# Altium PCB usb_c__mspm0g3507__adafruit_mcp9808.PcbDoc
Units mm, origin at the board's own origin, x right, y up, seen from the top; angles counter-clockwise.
Board outline 92 x 60 mm, 2 copper layers (Top, Bottom), stack 0 mm thick; 37 components, 30 nets, 190 pads, 49 vias.
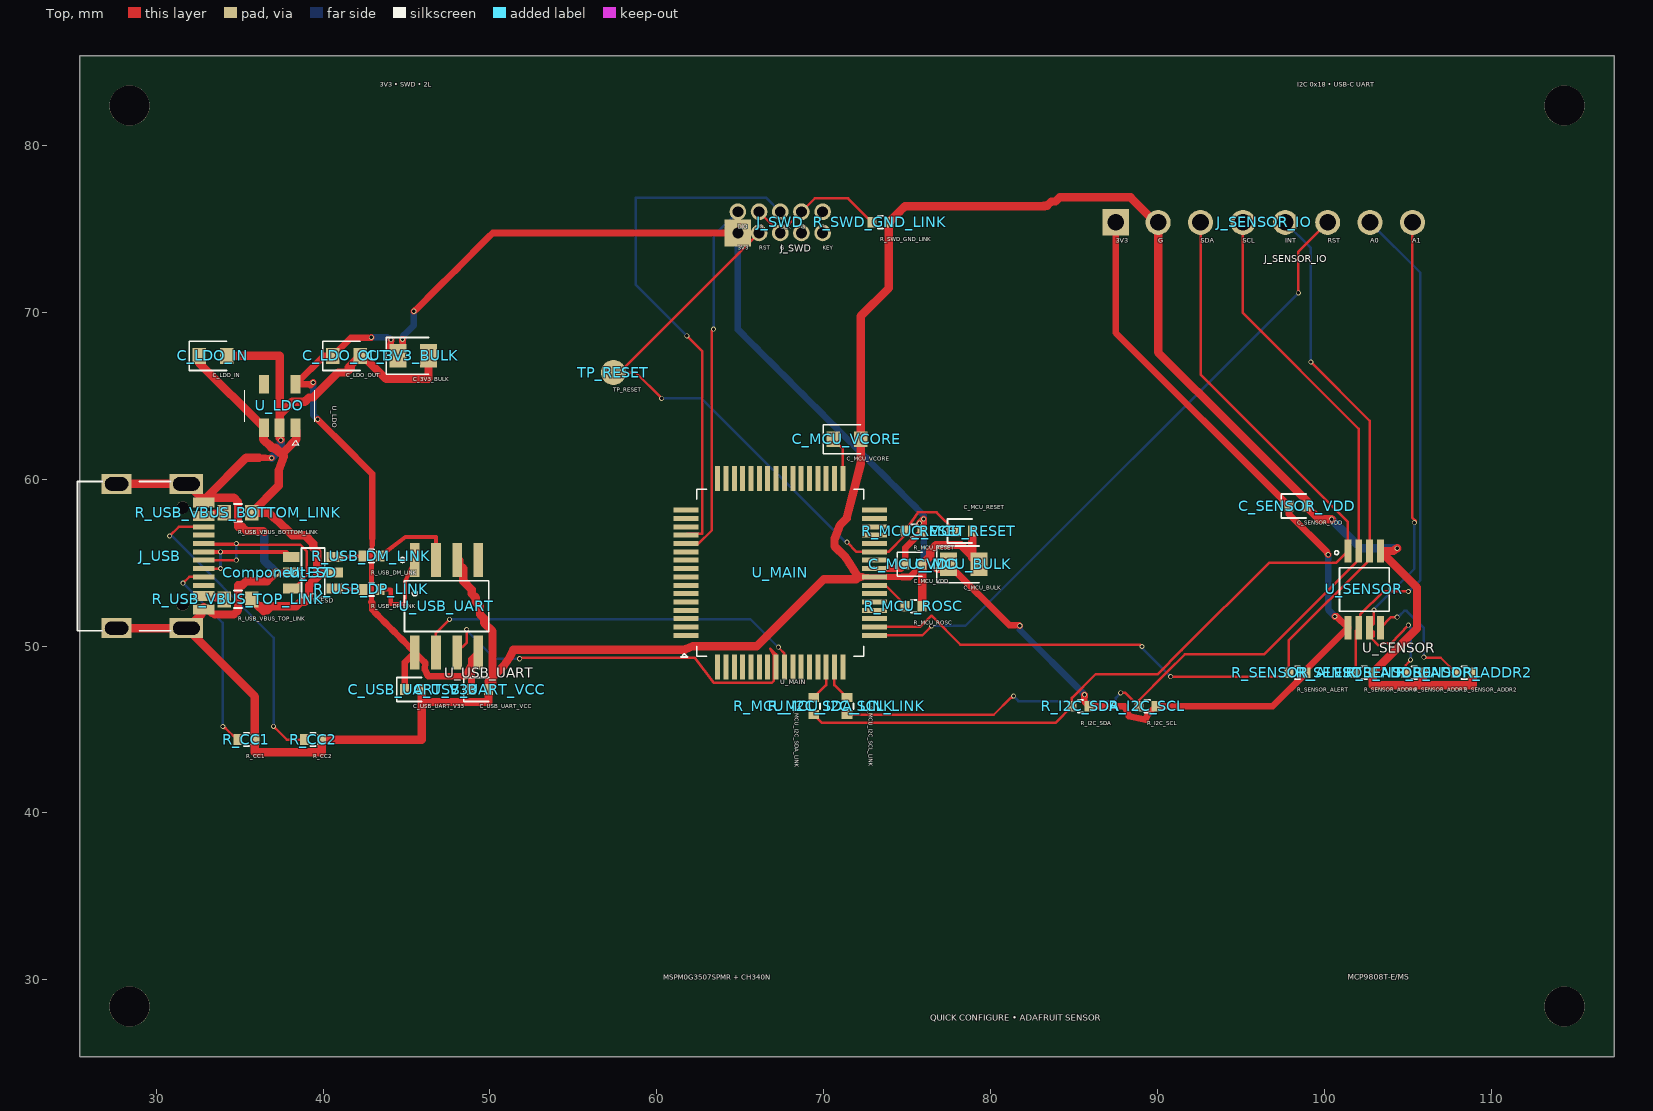
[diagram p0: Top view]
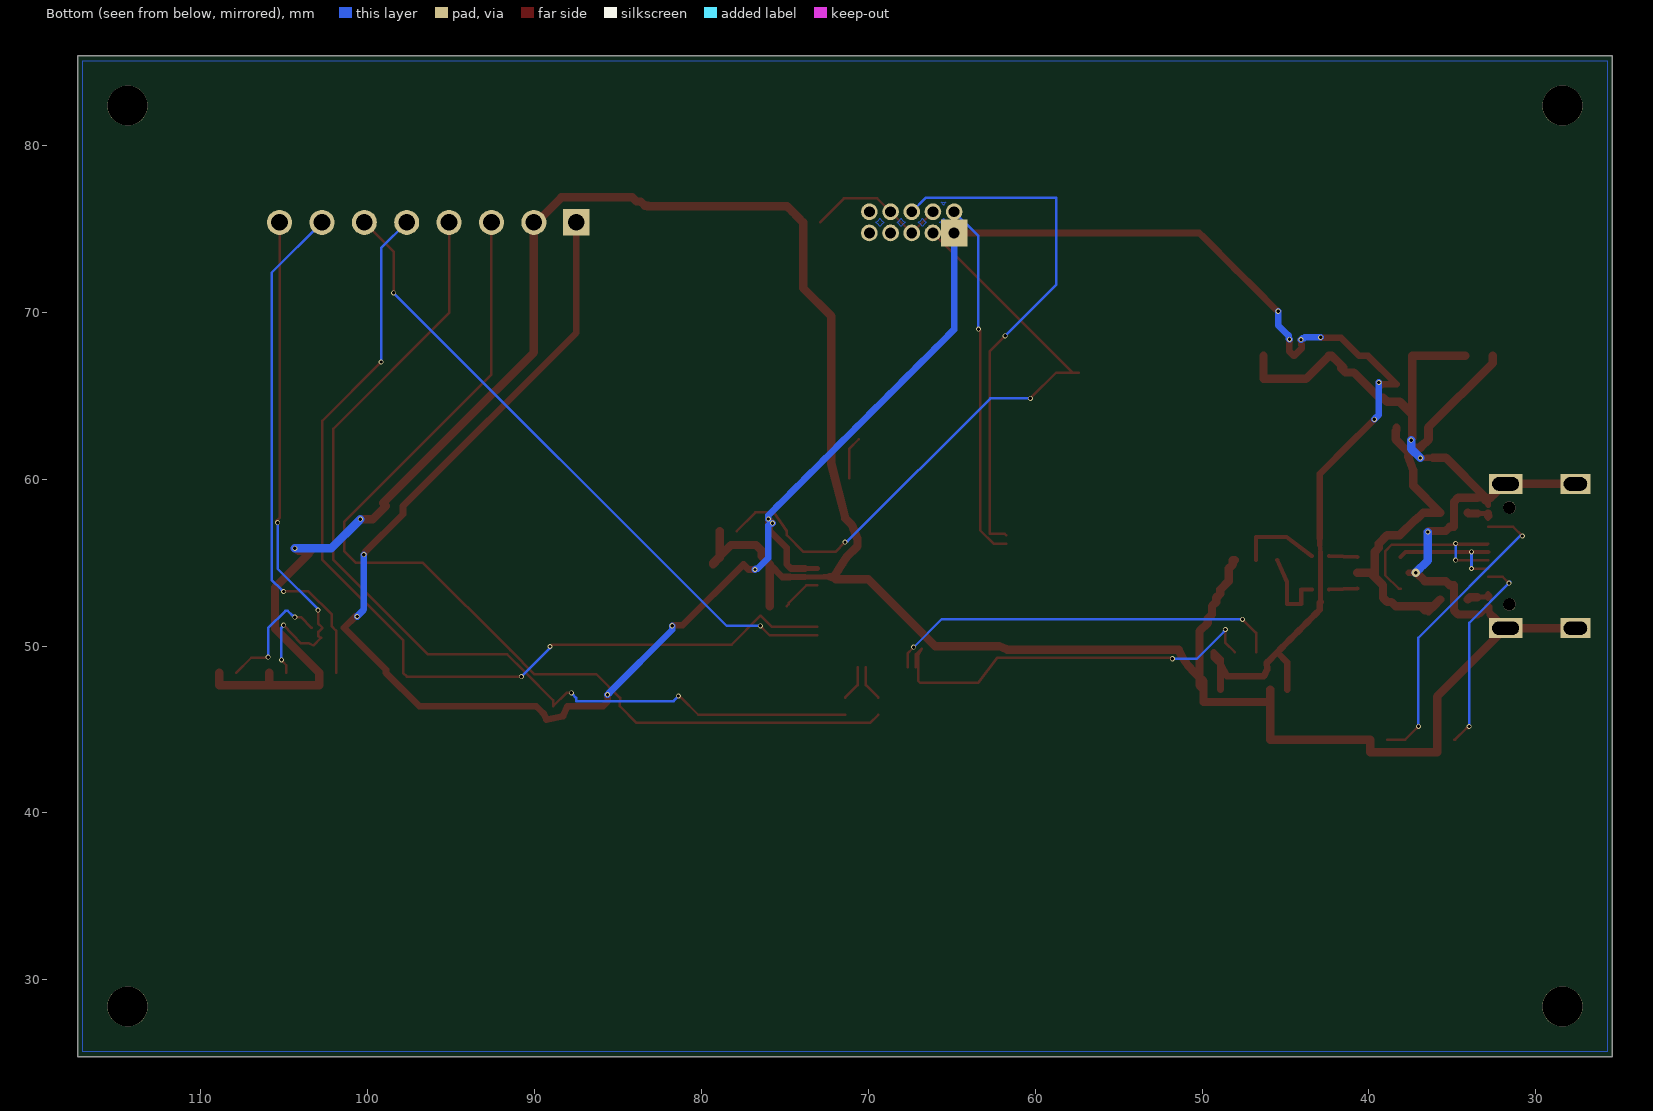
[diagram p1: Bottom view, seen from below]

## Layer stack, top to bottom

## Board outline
25.4,85.4 117.4,85.4 117.4,25.4 25.4,25.4

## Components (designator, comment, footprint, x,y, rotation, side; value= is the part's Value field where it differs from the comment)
C_3V3_BULK "" TSCIRCUIT-2.8500x1.4000mm 45.4,67.4 r0 top
C_LDO_IN "" TSCIRCUIT-2.4500x0.9500mm 33.4,67.4 r0 top
C_LDO_OUT "" TSCIRCUIT-2.4500x0.9500mm 41.4,67.4 r0 top
C_MCU_BULK "" TSCIRCUIT-2.8500x1.4000mm 78.4,54.9 r0 top
C_MCU_RESET "" TSCIRCUIT-1.5600x0.6400mm 78.4,56.9 r0 top
C_MCU_VCORE "" TSCIRCUIT-2.4500x0.9500mm 71.4,62.4 r0 top
C_MCU_VDD "" TSCIRCUIT-1.5600x0.6400mm 75.4,54.9 r0 top
C_SENSOR_VDD "" TSCIRCUIT-1.5600x0.6400mm 98.4,58.4 r0 top
C_USB_UART_V33 "" TSCIRCUIT-1.5600x0.6400mm 45.4,47.4 r0 top
C_USB_UART_VCC "" TSCIRCUIT-1.5600x0.6400mm 49.4,47.4 r0 top
Component-37 "" TSCIRCUIT-0.5000x0.5000mm 37.2,54.4 r0 top
J_SENSOR_IO "" TSCIRCUIT-19.2800x1.5000mm 96.4,75.4 r0 top
J_SWD "" TSCIRCUIT-6.0800x2.2700mm 67.4,75.4 r0 top
J_USB "" TSCIRCUIT-6.7732x9.8502mm 30.113,55.4 r90 top
R_CC1 "" TSCIRCUIT-1.5600x0.6400mm 35.4,44.4 r0 top
R_CC2 "" TSCIRCUIT-1.5600x0.6400mm 39.4,44.4 r0 top
R_I2C_SCL "" TSCIRCUIT-1.5600x0.6400mm 89.4,46.4 r0 top
R_I2C_SDA "" TSCIRCUIT-1.5600x0.6400mm 85.4,46.4 r0 top
R_MCU_I2C_SCL_LINK "" TSCIRCUIT-0.6400x1.5600mm 71.4,46.4 r270 top
R_MCU_I2C_SDA_LINK "" TSCIRCUIT-0.6400x1.5600mm 69.4,46.4 r270 top
R_MCU_RESET "" TSCIRCUIT-1.5600x0.6400mm 75.4,56.9 r0 top
R_MCU_ROSC "" TSCIRCUIT-1.5600x0.6400mm 75.4,52.4 r0 top
R_SENSOR_ADDR0 "" TSCIRCUIT-1.5600x0.6400mm 102.4,48.4 r0 top
R_SENSOR_ADDR1 "" TSCIRCUIT-1.5600x0.6400mm 105.4,48.4 r0 top
R_SENSOR_ADDR2 "" TSCIRCUIT-1.5600x0.6400mm 108.4,48.4 r0 top
R_SENSOR_ALERT "" TSCIRCUIT-1.5600x0.6400mm 98.4,48.4 r0 top
R_SWD_GND_LINK "" TSCIRCUIT-1.5600x0.6400mm 73.4,75.4 r0 top
R_USB_DM_LINK "" TSCIRCUIT-1.5600x0.6400mm 42.9,55.4 r0 top
R_USB_DP_LINK "" TSCIRCUIT-1.5600x0.6400mm 42.9,53.4 r0 top
R_USB_VBUS_BOTTOM_LINK "" TSCIRCUIT-2.4500x0.9500mm 34.9,58 r0 top
R_USB_VBUS_TOP_LINK "" TSCIRCUIT-2.4500x0.9500mm 34.9,52.8 r0 top
TP_RESET "" TSCIRCUIT-1.5000x1.5000mm 57.4,66.4 r0 top
U_ESD "" TSCIRCUIT-3.6000x2.5000mm 39.4,54.4 r0 top
U_LDO "" TSCIRCUIT-2.5000x3.7000mm 37.4,64.4 r270 top
U_MAIN "" TSCIRCUIT-12.8000x12.8000mm 67.4,54.4 r0 top
U_SENSOR "" TSCIRCUIT-2.3562x5.9969mm 102.4,53.4 r0 top
U_USB_UART "" TSCIRCUIT-4.3840x7.5712mm 47.4,52.4 r0 top

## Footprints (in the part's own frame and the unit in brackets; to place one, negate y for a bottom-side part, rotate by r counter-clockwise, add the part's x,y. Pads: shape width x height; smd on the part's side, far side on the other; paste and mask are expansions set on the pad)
TSCIRCUIT-0.5000x0.5000mm [mm]
TSCIRCUIT-0.6400x1.5600mm [mm]
  rect 0.54x0.64 smd: 1(-0.51,0) 2(0.51,0)
  silkscreen extent -0.15,-0.38 0.15,0.38
TSCIRCUIT-1.5000x1.5000mm [mm]
  round 1.5 smd: 1(0,0)
TSCIRCUIT-1.5600x0.6400mm [mm]
  rect 0.54x0.64 smd: 1(-0.51,0) 2(0.51,0)
  silkscreen extent -0.98,-0.72 0.51,0.72
TSCIRCUIT-2.3562x5.9969mm [mil]
  rect 15.98x55 smd: 1(-38.39,90.55) 2(-12.8,90.55) 3(12.8,90.55) 4(38.39,90.55) 5(38.39,-90.55) 6(12.8,-90.55) 7(-12.8,-90.55) 8(-38.39,-90.55)
  silkscreen extent -70,-51 59,91
TSCIRCUIT-2.4500x0.9500mm [mm]
  rect 0.8x0.95 smd: 1(-0.825,0) 2(0.825,0)
  silkscreen extent -1.42,-0.87 0.82,0.87
TSCIRCUIT-2.5000x3.7000mm [mm]
  rect 1.1x0.6 smd: 1(1.3,0.95) 2(1.3,0) 3(1.3,-0.95) 4(-1.3,-0.95) 5(-1.3,0.95)
  silkscreen extent -0.95,-2.1 2.35,2.1
TSCIRCUIT-2.8500x1.4000mm [mm]
  rect 1.025x1.4 smd: 1(-0.913,0) 2(0.913,0)
  silkscreen extent -1.63,-1.1 0.91,1.1
TSCIRCUIT-3.6000x2.5000mm [mm]
  rect 1x0.6 smd: 1(-1.3,-0.95) 2(-1.3,0) 3(-1.3,0.95) 4(1.3,0.95) 5(1.3,0) 6(1.3,-0.95)
  silkscreen extent -0.7,-1.49 0.7,1.49
TSCIRCUIT-4.3840x7.5712mm [mm]
  rect 0.574x2.036 smd: 1(-1.905,2.768) 2(-0.635,2.768) 3(0.635,2.768) 4(1.905,2.768) 5(1.905,-2.768) 6(0.635,-2.768) 7(-0.635,-2.768) 8(-1.905,-2.768)
  silkscreen extent -2.79,-1.52 2.53,2.92
TSCIRCUIT-6.0800x2.2700mm [mm]
  rect 1.6x1.6 hole 0.65: 1(-2.54,-0.635)
  round 1 hole 0.65: 2(-2.54,0.635) 3(-1.27,0.635) 4(0,0.635) 5(1.27,0.635) 6(2.54,0.635) 7(2.54,-0.635) 8(1.27,-0.635) 9(0,-0.635) 10(-1.27,-0.635)
TSCIRCUIT-6.7732x9.8502mm [mm]
  rect 0.3x1.3 smd: 1(-3.35,-2.737) 2(-3.05,-2.737) 3(-2.55,-2.737) 4(-2.25,-2.737) 5(-1.75,-2.737) 6(-1.25,-2.737) 7(-0.75,-2.737) 8(-0.25,-2.737) 9(0.25,-2.737) 10(0.75,-2.737) 11(1.25,-2.737) 12(1.75,-2.737) 13(2.55,-2.737) 14(2.25,-2.737) 15(3.35,-2.737) 16(3.05,-2.737)
  rect 1.2x2 hole 0.8 slot 1.6 at 90 deg: 17(-4.325,-1.693) 18(4.325,-1.693)
  rect 1.2x1.8 hole 0.8 slot 1.4 at 90 deg: 19(4.325,2.487) 20(-4.325,2.487)
  round 0.75 hole 0.75 unplated: NPTH-1(-2.9,-1.468) NPTH-2(2.9,-1.468)
  silkscreen extent -4.47,-0.75 4.47,4.83
TSCIRCUIT-12.8000x12.8000mm [mm]
  rect 1.5x0.3 smd: 1(-5.65,-3.75) 2(-5.65,-3.25) 3(-5.65,-2.75) 4(-5.65,-2.25) 5(-5.65,-1.75) 6(-5.65,-1.25) 7(-5.65,-0.75) 8(-5.65,-0.25) 9(-5.65,0.25) 10(-5.65,0.75) 11(-5.65,1.25) 12(-5.65,1.75) 13(-5.65,2.25) 14(-5.65,2.75) 15(-5.65,3.25) 16(-5.65,3.75) 33(5.65,3.75) 34(5.65,3.25) 35(5.65,2.75) 36(5.65,2.25) 37(5.65,1.75) 38(5.65,1.25) 39(5.65,0.75) 40(5.65,0.25) 41(5.65,-0.25) 42(5.65,-0.75) 43(5.65,-1.25) 44(5.65,-1.75) 45(5.65,-2.25) 46(5.65,-2.75) 47(5.65,-3.25) 48(5.65,-3.75)
  rect 0.3x1.5 smd: 17(-3.75,5.65) 18(-3.25,5.65) 19(-2.75,5.65) 20(-2.25,5.65) 21(-1.75,5.65) 22(-1.25,5.65) 23(-0.75,5.65) 24(-0.25,5.65) 25(0.25,5.65) 26(0.75,5.65) 27(1.25,5.65) 28(1.75,5.65) 29(2.25,5.65) 30(2.75,5.65) 31(3.25,5.65) 32(3.75,5.65) 49(3.75,-5.65) 50(3.25,-5.65) 51(2.75,-5.65) 52(2.25,-5.65) 53(1.75,-5.65) 54(1.25,-5.65) 55(0.75,-5.65) 56(0.25,-5.65) 57(-0.25,-5.65) 58(-0.75,-5.65) 59(-1.25,-5.65) 60(-1.75,-5.65) 61(-2.25,-5.65) 62(-2.75,-5.65) 63(-3.25,-5.65) 64(-3.75,-5.65)
  silkscreen extent -5.95,-5.05 5,5
TSCIRCUIT-19.2800x1.5000mm [mm]
  rect 1.6x1.6 hole 1: 1(-8.89,0)
  round 1.5 hole 1: 2(-6.35,0) 3(-3.81,0) 4(-1.27,0) 5(1.27,0) 6(3.81,0) 7(6.35,0) 8(8.89,0)

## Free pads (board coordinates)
  round 2.4 hole 2.4 unplated: NPTH-3(28.4,28.4) NPTH-4(114.4,28.4) NPTH-5(28.4,82.4) NPTH-6(114.4,82.4)

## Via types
v1: diameter 0.3, hole 0.2, Top to Bottom, 48 vias
v2: diameter 0.5, hole 0.2, Top to Bottom, 1 vias

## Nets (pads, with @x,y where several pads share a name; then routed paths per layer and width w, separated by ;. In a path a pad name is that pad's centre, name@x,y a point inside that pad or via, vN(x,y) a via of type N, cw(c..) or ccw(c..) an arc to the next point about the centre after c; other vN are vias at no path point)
".J_SWD > .pin2 to .U_MAIN > .pin12": J_SWD.2 U_MAIN.12 | length 21.6
  Top w0.15: U_MAIN.12 61.752,56.152 62.499,56.15 63.297,56.948 63.295,59.295 63.295,68.895 v1(63.4,69)
  Bottom w0.15: v1(63.4,69) 63.4,69.14 63.4,74.575 J_SWD.2
".J_SWD > .pin4 to .U_MAIN > .pin13": J_SWD.4 U_MAIN.13 | length 31.8
  Top w0.15: U_MAIN.13 61.833,56.733 62.711,56.736 62.714,67.686 v1(61.8,68.6)
  Bottom w0.15: v1(61.8,68.6) 61.756,68.644 58.745,71.655 58.745,76.868 66.567,76.868 J_SWD.4
".U_MAIN > .pin42 to .R_MCU_ROSC > .pin1": R_MCU_ROSC.1 U_MAIN.42 | length 2.4
  Top w0.15: U_MAIN.42 73.719,53.65 74.769,52.6 74.769,52.521 R_MCU_ROSC.1
GND: C_3V3_BULK.2 C_LDO_IN.2 C_LDO_OUT.2 C_MCU_BULK.2 C_MCU_RESET.2 C_MCU_VCORE.2 C_MCU_VDD.2 C_SENSOR_VDD.2 C_USB_UART_V33.2 C_USB_UART_VCC.2 J_SENSOR_IO.2 J_USB.1 J_USB.2 J_USB.15 J_USB.16 J_USB.17 J_USB.18 J_USB.19 J_USB.20 R_CC1.2 R_CC2.2 R_MCU_ROSC.2 R_SENSOR_ADDR0.2 R_SENSOR_ADDR1.2 R_SENSOR_ADDR2.2 R_SWD_GND_LINK.2 U_ESD.2 U_LDO.2 U_MAIN.41 U_SENSOR.4 U_USB_UART.3 | length 218.9
  Top w0.275: J_USB.2 J_USB.1@33.099,52.1 ; J_USB.16 J_USB.15@33.04,58.641
  Top w0.3: J_USB.1@32.699,51.9 J_USB.1 J_USB.1@32.849,52.2 ; J_USB.15@32.699,58.9 J_USB.15 ; J_USB.16@32.849,58.6 J_USB.15 ; J_USB.15@32.999,58.9 J_USB.15 ; J_USB.15@33.04,58.641 33.231,58.832 33.332,58.832 33.4,58.9 33.499,58.9 ; J_USB.1@33.099,52.1 33.299,51.9 33.499,51.9 ; U_MAIN.41@72.662,54.155 U_MAIN.41 73.144,54.15 73.237,54.15 73.331,54.15 73.425,54.15 73.519,54.15 73.612,54.15 73.706,54.15 U_MAIN.41@73.8,54.15
  Top w0.316: 72.3,54.158 72.553,54.155 U_MAIN.41
  Top w0.32: 72.3,54.16 U_MAIN.41@72.662,54.155
  Top w0.325: J_USB.16 J_USB.16@32.849,58.6
  Top w0.375: 36.16,61.292 36.538,61.286 v1(36.916,61.28) ; v1(37.463,62.343) v1@37.49,62.361 ; 61.68,49.775 61.735,49.83 ; U_MAIN.41@73.8,54.15 74.253,54.15 74.707,54.15
  Top w0.4: 37.2,54.4 U_ESD.2@37.6,54.4 ; v1@37.49,62.361 v1@37.49,62.387 ; 74.707,54.15 75.16,54.15 75.41,54.4 75.66,54.65 C_MCU_VDD.2
  Top w0.406: U_SENSOR.4@103.578,55.497 U_SENSOR.4 U_SENSOR.4@103.578,55.7
  Top w0.425: v1@37.4,62.477 v1@37.49,62.387
  Top w0.475: 71.951,54.019 72.275,54.16 72.3,54.16 ; 72.056,54.16 72.3,54.158
  Top w0.5: J_USB.20 J_USB.17 ; J_USB.19 J_USB.18 31.874,59.725 32.474,59.125 32.699,58.9 ; 32.699,51.9 32.474,51.675 31.874,51.075 J_USB.17 ; J_USB.1@32.849,52.2 J_USB.2 ; 32.999,58.9 35.392,61.292 36.16,61.292 ; 33.499,51.9 34.65,51.9 34.9,52.15 34.9,53.65 35.15,53.65 35.4,53.9 36.65,53.9 37.15,54.4 37.2,54.4 ; 33.499,58.9 34.65,58.9 34.9,58.65 34.9,57.15 35.15,57.15 35.4,56.9 36.409,56.9 v1(36.463,56.846) ; C_LDO_IN.2 37.4,67.4 U_LDO.2 ; v1@37.4,62.477 37.4,62.789 U_LDO.2 ; C_3V3_BULK.2 46.313,66.025 43.775,66.025 42.4,67.4 C_LDO_OUT.2 41.877,67.052 41.53,66.705 41.595,66.705 41.65,66.65 41.4,66.4 40.9,66.4 39.4,64.9 39.15,64.9 38.9,64.65 38.15,64.65 37.4,63.9 U_LDO.2 ; U_USB_UART.3 48.053,55.15 48.15,55.15 48.15,54.9 48.4,54.65 48.4,53.9 48.9,53.4 48.9,53.15 49.15,52.9 49.15,52.65 49.4,52.4 49.4,51.9 49.65,51.65 49.65,51.4 50.15,50.9 50.15,47.65 49.91,47.41 C_USB_UART_VCC.2 ; 61.68,49.775 51.9,49.775 51.4,49.775 51.219,49.381 51.007,49.081 50.795,48.781 50.5,48.486 50.205,48.191 49.91,47.895 C_USB_UART_VCC.2 ; 61.735,49.83 62.161,49.99 65.985,49.99 70.015,54.019 71.951,54.019 ; 72.056,54.16 71.815,54.542 71.573,54.924 71.331,55.305 70.65,55.987 70.65,56.4 70.986,57.26 71.094,57.369 71.377,57.651 72.225,60.937 72.225,61.425 72.225,61.912 C_MCU_VCORE.2 72.225,62.892 72.225,63.384 72.225,63.876 72.225,64.368 72.225,64.86 72.225,65.352 72.225,65.844 72.225,66.336 72.225,66.828 72.225,67.32 72.225,67.812 72.225,68.303 72.225,68.795 72.225,69.287 72.225,69.779 73.91,71.464 R_SWD_GND_LINK.2 74.232,75.722 74.554,76.044 74.876,76.366 74.951,76.366 75.438,76.366 75.925,76.366 76.413,76.366 76.9,76.366 77.387,76.366 77.875,76.366 78.362,76.366 78.849,76.366 79.337,76.366 79.824,76.366 80.311,76.366 80.799,76.366 81.286,76.366 81.773,76.366 82.261,76.366 82.748,76.366 83.235,76.366 83.202,76.4 83.4,76.4 83.65,76.65 83.9,76.65 84.15,76.9 88.4,76.9 89.9,75.4 J_SENSOR_IO.2 90.05,74.921 90.05,74.442 90.05,73.964 90.05,73.485 90.05,73.006 90.05,72.527 90.05,72.048 90.05,71.569 90.05,71.091 90.05,70.612 90.05,67.614 94.657,63.007 99.087,58.577 C_SENSOR_VDD.2 99.701,57.609 v1(100.447,57.609) ; R_MCU_ROSC.2 C_MCU_VDD.2 75.9,54.9 76.4,55.4 76.4,55.733 76.733,56.067 78.233,56.067 79.313,54.988 C_MCU_BULK.2 78.91,55.303 C_MCU_RESET.2 ; U_SENSOR.4@103.578,55.497 105.562,53.513 105.562,51.09 105.562,51.052 R_SENSOR_ADDR0.2 102.91,47.65 105.91,47.65 ; U_SENSOR.4@103.578,55.7 104.155,55.7 104.311,55.855 104.375,55.855 v1(104.378,55.858) ; R_SENSOR_ADDR2.2 108.91,47.65 105.91,47.65 ; J_USB.17 35.91,46.971 R_CC1.2 35.91,43.65 39.91,43.65 R_CC2.2 40.41,44.4 40.91,44.4 45.91,44.4 C_USB_UART_V33.2 45.91,46.65 49.91,46.65 C_USB_UART_VCC.2 ; 105.91,47.65 R_SENSOR_ADDR1.2 105.91,47.65
  Bottom w0.5: v1(36.463,56.846) 36.463,56.419 36.463,55.992 36.463,55.564 36.463,55.137 36.709,54.891 36.954,54.646 37.2,54.4 ; v1(36.916,61.28) 37.463,61.826 v1(37.463,62.343) ; v1(100.447,57.609) 100.54,57.516 102.198,55.858 v1(104.378,55.858)
MAIN_RESET: C_MCU_RESET.1 J_SWD.10 R_MCU_RESET.1 TP_RESET.1 U_MAIN.38 | length 38.9
  Top w0.15: v1(60.288,64.85) 60.277,64.861 58.738,66.4 TP_RESET.1 57.765,66.4 J_SWD.10 ; v1(71.398,56.234) 71.982,55.65 U_MAIN.38 73.889,55.65 74.889,56.651 R_MCU_RESET.1@74.889,56.899 ; R_MCU_RESET.1 75.65,58.014 76.776,58.014 C_MCU_RESET.1
  Bottom w0.15: v1(60.288,64.85) 62.685,64.85 71.242,56.293 71.339,56.293 v1(71.398,56.234)
MCU_I2C_SCL_LOCAL: R_MCU_I2C_SCL_LINK.1 U_MAIN.50 | length 2.2
  Top w0.15: U_MAIN.50 70.65,47.66 R_MCU_I2C_SCL_LINK.1
MCU_I2C_SDA_LOCAL: R_MCU_I2C_SDA_LINK.1 U_MAIN.51 | length 2.2
  Top w0.15: R_MCU_I2C_SDA_LINK.1 70.15,47.66 U_MAIN.51
MSPM0_VCORE: C_MCU_VCORE.1 U_MAIN.32 | length 2.6
  Top w0.15: C_MCU_VCORE.1 71.15,61.825 U_MAIN.32
SENSOR_ADDR0: J_SENSOR_IO.7 R_SENSOR_ADDR0.1 U_SENSOR.7 | length 30.7
  Top w0.15: R_SENSOR_ADDR0.1 101.89,50.915 U_SENSOR.7 102.159,51.185 102.159,51.886 103.558,53.284 v1(105.043,53.28)
  Bottom w0.15: J_SENSOR_IO.7 105.769,72.381 105.769,54.151 105.769,53.976 105.186,53.393 ; v1(105.043,53.28) 105.186,53.392
SENSOR_ADDR1: J_SENSOR_IO.8 R_SENSOR_ADDR1.1 U_SENSOR.6 | length 32.3
  Top w0.15: v1(102.985,52.155) 102.978,51.365 U_SENSOR.6 102.967,50.858 102.967,50.588 102.806,50.505 103.266,50.04 103.542,50.166 103.997,50.166 v1(105.046,51.261) ; R_SENSOR_ADDR1.1 104.89,48.857 105.097,49.064 105.097,49.1 v1(105.178,49.181) ; J_SENSOR_IO.8 105.29,57.693 105.494,57.489 v1(105.405,57.4)
  Bottom w0.15: v1(102.985,52.155) 102.995,52.16 102.995,52.229 105.405,54.639 v1(105.405,57.4) ; v1(105.046,51.261) 105.118,51.227 105.118,51.155 105.178,51.095 v1(105.178,49.181)
SENSOR_ADDR2: R_SENSOR_ADDR2.1 U_SENSOR.5 | length 7.5
  Top w0.15: U_SENSOR.5 104.017,51.742 v1(104.378,51.742) ; v1(105.978,49.342) 106.015,49.305 106.985,49.305 R_SENSOR_ADDR2.1
  Bottom w0.15: v1(104.378,51.742) 104.5,51.864 104.547,51.864 104.801,52.117 104.941,52.117 105.978,51.08 v1(105.978,49.342)
SENSOR_INT: J_SENSOR_IO.5 R_SENSOR_ALERT.1 U_MAIN.47 U_SENSOR.3 | length 57.9
  Top w0.15: U_MAIN.47 75.785,51.15 76.46,51.825 78.203,50.082 88.965,50.082 88.979,50.082 v1(89.079,49.982) ; v1(90.798,48.172) 97.662,48.172 R_SENSOR_ALERT.1 97.891,50.364 102.736,55.189 U_SENSOR.3 102.725,63.51 v1(99.203,67.032)
  Bottom w0.15: v1(89.079,49.982) 89.079,49.887 90.767,48.199 90.771,48.199 v1(90.798,48.172) ; J_SENSOR_IO.5 99.2,73.87 99.2,67.035 v1(99.203,67.032)
SENSOR_RESET: J_SENSOR_IO.6 U_MAIN.48 | length 38.9
  Top w0.15: U_MAIN.48 75.912,50.65 76.363,51.101 76.363,51.109 v1(76.476,51.222) ; v1(98.453,71.181) 98.453,73.643 J_SENSOR_IO.6
  Bottom w0.15: v1(76.476,51.222) 78.494,51.222 98.451,71.179 v1(98.453,71.181)
SENSOR_SCL: J_SENSOR_IO.4 R_I2C_SCL.1 R_MCU_I2C_SCL_LINK.2 U_SENSOR.2 | length 58.9
  Top w0.15: R_MCU_I2C_SCL_LINK.2 80.196,45.89 81.224,46.918 81.301,46.918 v1(81.391,47.008) ; v1(87.8,47.2) 88.09,47.2 R_I2C_SCL.1 88.89,46.758 90.581,48.449 91.643,49.511 96.392,49.511 102.083,55.187 U_SENSOR.2 102.075,63.027 95.13,69.972 J_SENSOR_IO.4
  Bottom w0.15: v1(81.391,47.008) 81.68,46.711 87.52,46.703 87.52,46.898 87.743,47.121 87.743,47.143 v1(87.8,47.2)
SENSOR_SDA: J_SENSOR_IO.3 R_I2C_SDA.1 R_MCU_I2C_SDA_LINK.2 U_SENSOR.1 | length 60.2
  Top w0.15: R_MCU_I2C_SDA_LINK.2 69.891,45.399 83.889,45.399 R_I2C_SDA.1 84.881,46.9 86.306,48.316 90.014,48.311 91.461,49.758 96.695,54.993 100.718,54.993 U_SENSOR.1 101.425,57.45 92.59,66.285 J_SENSOR_IO.3
swd-ground-1-to-2: J_SWD.3 J_SWD.5 J_SWD.9 R_SWD_GND_LINK.1 | length 8.8
  Top w0.15: J_SWD.3 J_SWD.9 J_SWD.5 69.481,76.846 71.471,76.846 71.471,76.819 R_SWD_GND_LINK.1
UART_MSP_RX: U_MAIN.57 U_USB_UART.6 | length 24.8
  Top w0.15: U_USB_UART.6 48.6,50.197 v1(48.6,51) ; v1(51.78,49.245) 51.851,49.245 51.908,49.302 62.276,49.301 63.412,47.806 66.9,47.806 67.012,47.919 67.012,49.494 66.797,49.853 67.15,49.5 U_MAIN.57
  Bottom w0.15: v1(48.6,51) 48.697,50.903 48.697,50.851 50.303,49.245 v1(51.78,49.245)
UART_MSP_TX: U_MAIN.56 U_USB_UART.7 | length 24.1
  Top w0.15: U_USB_UART.7 46.765,50.794 v1(47.579,51.608) ; v1(67.281,49.936) 67.342,49.875 67.342,49.872 67.65,49.564 U_MAIN.56
  Bottom w0.15: v1(47.579,51.608) 47.586,51.615 47.758,51.615 65.602,51.615 v1(67.281,49.936)
usb-dm-device: R_USB_DM_LINK.1 U_ESD.4 | length 1.7
  Top w0.25: U_ESD.4 R_USB_DM_LINK.1
usb-dm-port-tie: J_USB.7 J_USB.9 U_ESD.3 | length 8.4
  Top w0.15: J_USB.7 v1(33.85,54.65) ; J_USB.9 v1(33.85,55.65)
  Top w0.25: J_USB.9 37.8,55.65 U_ESD.3
  Bottom w0.15: v1(33.85,54.65) v1(33.85,55.65)
usb-dm-uart: R_USB_DM_LINK.2 U_USB_UART.2 | length 5.1
  Top w0.25: R_USB_DM_LINK.2 44.95,56.55 46.765,56.55 U_USB_UART.2
usb-dp-device: R_USB_DP_LINK.1 U_ESD.6 | length 1.7
  Top w0.25: U_ESD.6 R_USB_DP_LINK.1
usb-dp-port-tie: J_USB.8 J_USB.10 U_ESD.1 | length 14
  Top w0.15: J_USB.8 v1(34.8,55.15) ; v1(34.8,56.15) J_USB.10 32.913,56.086 38.628,56.086 39.014,55.7 39.023,54.252 38.209,53.445 U_ESD.1
  Bottom w0.15: v1(34.8,55.15) v1(34.8,56.15)
usb-dp-uart: R_USB_DP_LINK.2 U_USB_UART.1 | length 5.1
  Top w0.25: R_USB_DP_LINK.2 44.05,53.4 44.05,52.53 44.9,52.53 44.9,53.85 U_USB_UART.1
USB_CC1: J_USB.6 R_CC1.1 | length 12.4
  Top w0.15: v1(31.606,53.779) 31.978,54.15 J_USB.6 ; v1(33.986,45.184) 34.102,45.068 34.167,45.068 34.835,44.4 R_CC1.1
  Bottom w0.15: v1(31.606,53.779) 31.536,53.85 33.986,51.399 v1(33.986,45.184)
USB_CC2: J_USB.12 R_CC2.1 | length 18.6
  Top w0.15: v1(30.8,56.6) 31.35,57.15 J_USB.12 ; v1(37.029,45.192) 37.162,45.059 ; 37.162,45.057 37.82,44.4 R_CC2.1
  Bottom w0.15: v1(30.8,56.6) 30.824,56.624 30.908,56.624 37.029,50.503 v1(37.029,45.192)
USB_VBUS_BOTTOM_LOCAL: J_USB.13 J_USB.14 R_USB_VBUS_BOTTOM_LINK.1 | length 1.5
  Top w0.3: J_USB.14 J_USB.14@32.849,57.8 ; J_USB.13 32.927,57.95 33.005,57.95 33.083,57.95 33.161,57.95 33.239,57.95 33.317,57.95 33.394,57.95 33.472,57.95 33.499,57.95
  Top w0.475: J_USB.13@32.849,57.8 J_USB.13 ; 33.499,57.95 R_USB_VBUS_BOTTOM_LINK.1@33.762,57.95
  Top w0.5: R_USB_VBUS_BOTTOM_LINK.1@33.762,57.95 34.025,57.95 R_USB_VBUS_BOTTOM_LINK.1
USB_VBUS_TOP_LOCAL: J_USB.3 J_USB.4 R_USB_VBUS_TOP_LINK.1 | length 1.6
  Top w0.3: J_USB.4 32.849,53 J_USB.3 32.944,52.958 33.032,52.939 33.499,52.939
  Top w0.5: 33.499,52.939 33.675,52.939 33.936,52.939 R_USB_VBUS_TOP_LINK.1
VBUS5: C_LDO_IN.1 R_USB_VBUS_BOTTOM_LINK.2 R_USB_VBUS_TOP_LINK.2 U_ESD.5 U_LDO.1 U_LDO.3 | length 35
  Top w0.5: C_LDO_IN.1 32.575,66.975 U_LDO.3 ; U_LDO.1 38.35,62.95 38.4,62.9 38.4,62.4 37.65,61.65 37.4,61.65 37.15,61.9 36.9,61.9 36.4,62.4 36.4,63.15 U_LDO.3 ; U_ESD.5 39.9,54.4 39.15,53.65 ; U_LDO.3 36.451,62.713 36.453,62.325 37.65,61.4 37.339,60.535 37.339,59.614 R_USB_VBUS_BOTTOM_LINK.2 36.063,58 36.401,58 36.74,58 37.083,57.657 37.112,57.657 37.185,57.584 37.216,57.584 38.15,56.65 38.9,56.65 39.4,56.15 39.4,55.9 39.65,55.65 39.65,54.15 39.15,53.65 ; 38.4,52.4 36.9,52.4 36.65,52.15 36.4,52.15 36.4,52.125 36.425,52.1 36.075,52.45 R_USB_VBUS_TOP_LINK.2 36.057,52.468 36.125,52.4 38.4,52.4 ; 38.4,52.4 38.65,52.65 ; 38.4,52.4 38.65,52.65 ; 38.65,52.65 38.9,52.65 ; 38.65,52.65 38.9,52.65 ; 38.9,52.65 39.15,52.9 ; 38.9,52.65 39.15,52.9 ; 39.15,52.9 39.15,53.65 ; 39.15,52.9 39.15,53.65
VCC_3V3: C_3V3_BULK.1 C_LDO_OUT.1 C_MCU_BULK.1 C_MCU_VDD.1 C_SENSOR_VDD.1 C_USB_UART_V33.1 C_USB_UART_VCC.1 J_SENSOR_IO.1 J_SWD.1 R_I2C_SCL.2 R_I2C_SDA.2 R_MCU_RESET.2 R_SENSOR_ALERT.2 U_LDO.5 U_MAIN.40 U_SENSOR.8 U_USB_UART.5 U_USB_UART.8 | length 155.9
  Top w0.262: 42.9,55.65 42.921,55.861 42.942,56.072
  Top w0.275: 42.9,53.025 42.9,53.4 42.9,53.775 42.9,54.15 ; 42.9,54.9 42.9,55.275 42.9,55.65
  Top w0.288: 42.9,52.65 42.9,53.025 ; 42.9,54.15 42.9,54.525 42.9,54.9
  Top w0.3: U_MAIN.40 73.15,54.65 73.25,54.65 73.35,54.65 73.45,54.65 73.55,54.65 73.65,54.65 73.75,54.65 U_MAIN.40@73.8,54.65
  Top w0.312: 42.942,56.072 42.942,56.459
  Top w0.4: v1(39.4,65.8) 39.25,65.65 39.224,65.65 39.174,65.7 38.899,65.7 38.625,65.7 U_LDO.5 40.05,67.4 C_LDO_OUT.1 41.663,68.488 42.876,68.5 v1(42.889,68.512) ; v1(39.673,63.596) 39.945,63.324 40.218,63.051 40.49,62.779 40.763,62.506 41.035,62.234 41.307,61.962 41.58,61.689 41.852,61.417 42.125,61.144 42.397,60.872 42.67,60.599 42.942,60.327 42.942,59.94 42.942,59.553 42.942,59.167 42.942,58.78 42.942,58.393 42.942,58.006 42.942,57.619 42.942,57.233 42.942,56.846 42.942,56.459 ; 42.9,52.65 42.942,52.591 42.942,52.204 42.942,52.185 43.197,51.93 43.453,51.674 43.708,51.419 43.963,51.164 44.218,50.909 44.474,50.653 44.729,50.398 44.984,50.143 45.24,49.887 U_USB_UART.8 ; v1(44.072,68.366) 44.017,67.871 C_3V3_BULK.1 44.634,67.546 44.781,67.693 44.768,68.039 v1(44.755,68.386) ; C_USB_UART_V33.1 44.89,49.027 U_USB_UART.8 ; v1(45.438,70.073) 45.494,70.129 45.53,70.129 45.803,70.402 46.076,70.675 46.348,70.947 46.621,71.22 46.894,71.493 47.166,71.765 47.439,72.038 47.712,72.311 47.984,72.584 48.257,72.856 48.53,73.129 48.802,73.402 49.075,73.674 49.348,73.947 49.621,74.22 49.893,74.492 50.166,74.765 50.563,74.765 50.96,74.765 51.357,74.765 51.754,74.765 52.152,74.765 52.549,74.765 52.946,74.765 53.343,74.765 53.74,74.765 54.137,74.765 54.534,74.765 54.932,74.765 55.329,74.765 55.726,74.765 56.123,74.765 56.52,74.765 56.917,74.765 57.314,74.765 57.712,74.765 58.109,74.765 58.506,74.765 58.903,74.765 59.3,74.765 59.697,74.765 60.094,74.765 60.491,74.765 60.889,74.765 61.286,74.765 61.683,74.765 62.08,74.765 62.477,74.765 62.874,74.765 63.271,74.765 63.669,74.765 64.066,74.765 64.463,74.765 J_SWD.1 ; C_USB_UART_VCC.1 48.89,49.217 U_USB_UART.5 49.305,49.345 49.093,49.129 48.881,48.912 48.5,48.2 46.3,48.2 46.1,48.6 46.115,49.012 45.908,49.219 45.702,49.425 U_USB_UART.8 ; U_MAIN.40@73.8,54.65 73.85,54.65 74.64,54.65 C_MCU_VDD.1 74.89,55.88 R_MCU_RESET.2 ; v1(75.75,57.375) 75.994,57.614 75.91,57.53 75.91,57.215 R_MCU_RESET.2 ; v1(76,57.62) 76,57.305 76,56.99 R_MCU_RESET.2 ; v1(76.791,54.592) 77.18,54.592 77.334,54.746 C_MCU_BULK.1 81.136,51.252 81.726,51.252 v1(81.755,51.223) ; v1(85.631,47.096) 85.617,46.693 R_I2C_SDA.2 86.264,46.4 86.619,46.4 86.973,46.4 87.327,46.4 87.682,46.4 88.036,46.4 88.3,45.8 89.3,45.6 89.484,45.974 ; J_SENSOR_IO.1 87.51,68.78 C_SENSOR_VDD.1 97.89,57.905 100.191,55.603 100.191,55.534 v1(100.238,55.487) ; v1(100.64,51.776) 100.749,51.776 U_SENSOR.8 98.91,48.585 R_SENSOR_ALERT.2 96.91,46.4 R_I2C_SCL.2 89.697,46.187 89.484,45.974 ; 89.484,45.974 89.474,45.974 89.484,45.974
  Bottom w0.4: v1(39.4,65.8) 39.4,65.414 39.4,65.028 39.4,64.641 39.4,64.255 39.4,63.869 39.624,63.645 v1(39.673,63.596) ; v1(42.889,68.512) 43.839,68.501 43.882,68.458 43.979,68.458 v1(44.072,68.366) ; v1(44.755,68.386) 44.795,68.425 44.795,68.59 45.009,68.805 45.224,69.019 45.438,69.233 45.438,69.513 45.438,69.793 v1(45.438,70.073) ; J_SWD.1 64.86,74.379 64.86,73.993 64.86,73.608 64.86,73.222 64.86,72.836 64.86,72.45 64.86,72.065 64.86,71.679 64.86,71.293 64.86,70.907 64.86,70.521 64.86,70.136 64.86,69.75 64.86,69.364 64.86,68.978 65.138,68.7 65.417,68.421 65.695,68.143 65.974,67.864 66.252,67.586 66.531,67.308 66.809,67.029 67.088,66.751 67.366,66.472 67.644,66.194 67.923,65.915 68.201,65.637 68.48,65.358 68.758,65.08 69.037,64.802 69.315,64.523 69.594,64.245 69.872,63.966 70.151,63.688 70.429,63.409 70.707,63.131 70.986,62.852 71.264,62.574 71.543,62.295 71.821,62.017 72.1,61.739 72.378,61.46 72.657,61.182 72.935,60.903 73.213,60.625 73.492,60.346 73.77,60.068 74.049,59.789 74.327,59.511 74.606,59.233 74.884,58.954 75.163,58.676 75.441,58.397 75.719,58.119 75.998,57.84 75.998,57.622 v1(76,57.62) ; v1(75.75,57.375) 76,57.23 76,56.84 76,56.45 76,56.06 76,55.67 76,55.28 76.214,55.066 76.428,54.851 76.643,54.637 76.745,54.637 v1(76.791,54.592) ; v1(81.755,51.223) 81.755,50.987 85.511,47.231 85.511,47.191 v1(85.631,47.096) ; v1(100.238,55.487) 100.238,52.203 100.567,51.874 100.567,51.849 v1(100.64,51.776)
pads on no net: J_SWD.6 J_SWD.7 J_SWD.8 J_USB.5 J_USB.11 J_USB.NPTH-1 J_USB.NPTH-2 U_LDO.4 U_MAIN.1 U_MAIN.2 U_MAIN.3 U_MAIN.4 U_MAIN.5 U_MAIN.6 U_MAIN.7 U_MAIN.8 U_MAIN.9 U_MAIN.10 U_MAIN.11 U_MAIN.14 U_MAIN.15 U_MAIN.16 U_MAIN.17 U_MAIN.18 U_MAIN.19 U_MAIN.20 U_MAIN.21 U_MAIN.22 U_MAIN.23 U_MAIN.24 U_MAIN.25 U_MAIN.26 U_MAIN.27 U_MAIN.28 U_MAIN.29 U_MAIN.30 U_MAIN.31 U_MAIN.33 U_MAIN.34 U_MAIN.35 U_MAIN.36 U_MAIN.37 U_MAIN.39 U_MAIN.43 U_MAIN.44 U_MAIN.45 U_MAIN.46 U_MAIN.49 U_MAIN.52 U_MAIN.53 U_MAIN.54 U_MAIN.55 U_MAIN.58 U_MAIN.59 U_MAIN.60 U_MAIN.61 U_MAIN.62 U_MAIN.63 U_MAIN.64 U_USB_UART.4
copper on no net:
  other v2: 37.2,54.4

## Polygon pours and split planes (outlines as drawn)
GND on Bottom (solid): 117.1,85.1 25.7,85.1 25.7,25.7 117.1,25.7
GND on Bottom (solid): 65.633,76.593 65.357,76.593 65.39,76.565 65.484,76.452 65.495,76.43 65.506,76.452 65.6,76.565
GND on Bottom (solid): 65.495,75.64 65.484,75.618 65.399,75.515 65.591,75.515 65.506,75.618
GND on Bottom (solid): 65.61,75.496 65.61,75.304 65.713,75.389 65.735,75.4 65.713,75.411
GND on Bottom (solid): 69.305,75.64 69.294,75.618 69.2,75.505 69.087,75.411 69.065,75.4 69.087,75.389 69.2,75.295 69.294,75.182 69.305,75.16 69.316,75.182 69.41,75.295 69.523,75.389 69.545,75.4 69.523,75.411 69.41,75.505 69.316,75.618
GND on Bottom (solid): 68.035,75.64 68.024,75.618 67.93,75.505 67.817,75.411 67.795,75.4 67.817,75.389 67.93,75.295 68.024,75.182 68.035,75.16 68.046,75.182 68.14,75.295 68.253,75.389 68.275,75.4 68.253,75.411 68.14,75.505 68.046,75.618
GND on Bottom (solid): 66.765,75.64 66.754,75.618 66.66,75.505 66.547,75.411 66.525,75.4 66.547,75.389 66.66,75.295 66.754,75.182 66.765,75.16 66.776,75.182 66.87,75.295 66.983,75.389 67.005,75.4 66.983,75.411 66.87,75.505 66.776,75.618

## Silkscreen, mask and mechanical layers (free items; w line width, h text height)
Top Overlay:
  text "3V3 • SWD • 2L" at 43.4,83.4 h0.48
  text "I2C 0x18 • USB-C UART" at 98.4,83.4 h0.5
  text "MSPM0G3507SPMR + CH340N" at 60.4,29.9 h0.52
  text "MCP9808T-E/MS" at 101.4,29.9 h0.55
  text "QUICK CONFIGURE • ADAFRUIT SENSOR" at 76.4,27.4 h0.65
